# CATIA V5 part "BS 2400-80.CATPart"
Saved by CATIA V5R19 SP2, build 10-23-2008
Part number: BS 2400-80
Bounding box of the stored display mesh (mm): x -37.351 to 37.351, y -37.351 to 37.351, z 0 to 205
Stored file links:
  C:\Users\Bora\Desktop\3D Katı model\BS serisi\BS 2400\BS 2400-80.CATPart
  C:\Program Files\Dassault Systemes\B19\intel_a\reffiles\standard\MetricThickPitch.txt
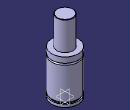
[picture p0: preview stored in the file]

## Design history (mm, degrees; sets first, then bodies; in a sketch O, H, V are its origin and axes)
Body1 (main body)
  Sketch1 on yz-plane, origin (0, 0, 0), H (0, 1, 0), V (0, 0, 1)
    point P1 (22.5, 204)
    point P3 (22.5, 204)
    point P7 (37.5, 108.5)
    point P9 (37.5, 108.5)
    point P10 (37.5, 103.5)
    point P14 (37.5, 103.5)
    line L1 (22.5, 204) -> (22.5, 124)
    arc A1 centre (21.5, 204) radius 1 from (22.5, 204) to (21.5, 205) ccw
    line L2 (37.5, 0) -> (37.5, 8)
    line L3 (37.5, 108.5) -> (37.5, 124)
    arc A2 centre (37.5, 106) radius 2.5 from (37.5, 108.5) to (37.5, 103.5) ccw
    line L4 (34.5, 13) -> (34.5, 8)
    line L5 (37.5, 13) -> (37.5, 103.5)
    line L6 (21.5, 205) -> (0, 205)
    point P15 (0, 205)
    line L7 (22.5, 124) -> (37.5, 124)
    line L8 (0, 0) -> (37.5, 0)
    line L9 (34.5, 13) -> (37.5, 13)
    line L10 (34.5, 8) -> (37.5, 8)
    coincidence: P15 V, P1 P3, P7 P9, P10 P14
    tangency: L6 A1
    horizontal: L7 H, L8 H, L9 H, L10 H
  Shaft1: profile Sketch1, axis Sketch1.V, angle 360
  Sketch2 on face of Shaft1 from Sketch1.L8, origin (0, 0, 0), H (1, 0, 0), V (0, -1, 0)
    point P1 (20, 0)
    distance P1 V = 20
  Hole1: placed by Sketch2, at (20, 0, 0) direction (0, 0, 1), diameter 6.647, depth 5, threaded "M8", thread diameter 8, thread depth 5, pitch 1.25
  CircPattern1: of Hole1, instances 4, angular step 90, axis from xy-plane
